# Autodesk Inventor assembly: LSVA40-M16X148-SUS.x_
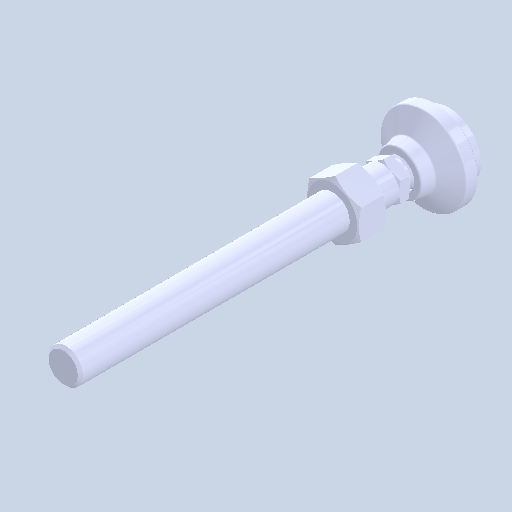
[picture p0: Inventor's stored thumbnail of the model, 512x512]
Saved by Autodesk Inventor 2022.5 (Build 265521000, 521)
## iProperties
Created: 2024-08
Part Number: LSVA40-M16X148-SUS.x_
Document SubType Name: Assembly
Designer: ImaoCorp
Author: ImaoCorp
Sending System: SOLIDWORKS 2022-2022290
MC: AMD64
MC_MODEL: Intel64 Family 6 Model 60 Stepping 3, GenuineIntel
OS: Windows_NT
FRU: Parasolid Version 33.1, build 260,  4-25-2022
FORMAT: text
GUISE: transmit
KEY: FILELSVA40-M16X148-SUS.x_t
DATE: Fri Aug 23 16:07:45 2024
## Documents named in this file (4)
- X:\14_SW2022-Inv2022\06_2024-10新製品(SME)\ELS_データ\l\lsva40-m16x148-sus\LSVA40-M16X148-SUS.x_.iam
- X:\14_SW2022-Inv2022\06_2024-10新製品(SME)\ELS_データ\l\lsva40-m16x148-sus\LSVA40-M16X148-SUS_01.ipt
- X:\14_SW2022-Inv2022\06_2024-10新製品(SME)\ELS_データ\l\lsva40-m16x148-sus\LSVA40-M16X148-SUS_02.ipt
- X:\14_SW2022-Inv2022\06_2024-10新製品(SME)\ELS_データ\l\lsva40-m16x148-sus\LSVA40-M16X148-SUS_03.ipt
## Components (3 placed, 3 different names)
1. LSVA40-M16X148-SUS_01
2. LSVA40-M16X148-SUS_02
3. LSVA40-M16X148-SUS_03
